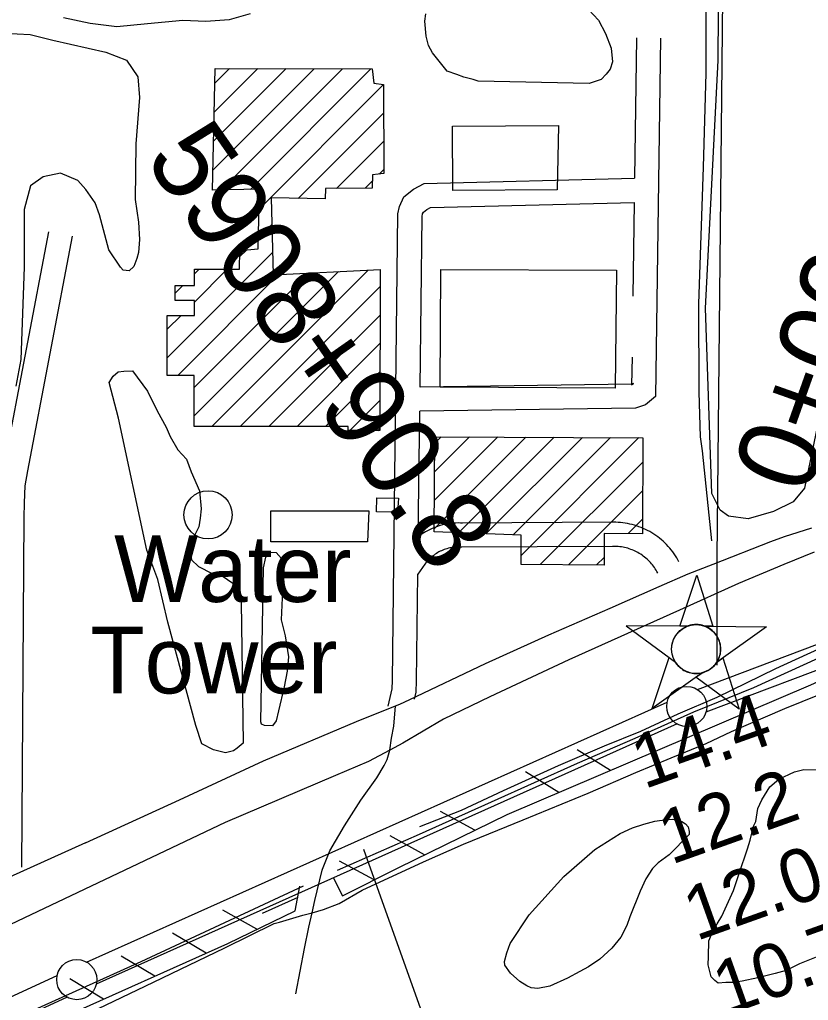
# Model space of a CAD drawing. Extents: x 3598634 to 3636690, y 517270 to 542944.
# Drawn here: x 3613422 to 3614405, y 537102 to 538324 of the extents above; entities that cross this region are included whole.
import ezdxf

# ---------------------------------------------------------------- set-up
doc = ezdxf.new("R2010")
doc.units = 0
for name, color, linetype in [('V-BLDG-OTLN', 7, 'Continuous'), ('V-CHAN-NAID', 7, 'Continuous'), ('V-DOMW-IDEN', 7, 'Continuous'), ('V-DOMW-TANK', 7, 'Continuous'), ('V-FLOD-BASE', 7, 'Continuous'), ('V-LEVE-TOET', 7, 'Continuous'), ('V-RIVR-RANG', 7, 'Continuous'), ('V-ROAD-CNTR', 7, 'Continuous'), ('V-RRAP-FSHR', 7, 'Continuous'), ('V-SITE-VEGE', 7, 'Continuous'), ('V-SURV-IDEN', 7, 'Continuous'), ('V-SURV-LINE', 7, 'Continuous'), ('V-TOPO-BNDY', 7, 'Continuous'), ('V-TOPO-SHOR', 7, 'Continuous')]:
    doc.layers.add(name, color=color, linetype=linetype)

msp = doc.modelspace()

# ---------------------------------------------------------------- linework, layer by layer
at = {"layer": 'V-BLDG-OTLN'}
for p, q in [((3613663.3, 538136.7), (3613789.6, 538263)), ((3613664.1, 538172.8), (3613754.4, 538263.1)), ((3613664.9, 538209), (3613719.2, 538263.3)), ((3613665.7, 538245.1), (3613684, 538263.4)), ((3613673.9, 538111.9), (3613824.8, 538262.9)), ((3613710.1, 538112.7), (3613860.1, 538262.7)), ((3613720.8, 538088.1), (3613875.9, 538243.2)), ((3613769.5, 538101.5), (3613876.1, 538208)), ((3613817.4, 538113.9), (3613876.2, 538172.7)), ((3613870.5, 538131.7), (3613876.2, 538137.5)), ((3613853, 538114.2), (3613862.1, 538123.3)), ((3613720, 538051.9), (3613736.7, 538068.7)), ((3613696.5, 538028.5), (3613705.4, 538037.3)), ((3613606.3, 537902.9), (3613737.5, 538034.1)), ((3613640.2, 538007.5), (3613646.1, 538013.4)), ((3613640.4, 537972.3), (3613681.2, 538013.2)), ((3613619.6, 537880.8), (3613745.2, 538006.5)), ((3613639.7, 537865.6), (3613782.5, 538008.3)), ((3613639.8, 537830.3), (3613819.7, 538010.2)), ((3613662, 537817.2), (3613856.9, 538012.1)), ((3613616.2, 537983.5), (3613625.6, 537992.9)), ((3613697.4, 537817.2), (3613871.8, 537991.6)), ((3613606.3, 537938.3), (3613623.7, 537955.7)), ((3613732.8, 537817.2), (3613871.7, 537956.1)), ((3613768.1, 537817.2), (3613871.5, 537920.6)), ((3613803.5, 537817.3), (3613871.4, 537885.1)), ((3613833.8, 537812.2), (3613871.2, 537849.6)), ((3613869, 537812.1), (3613871.1, 537814.1)), ((3613939.1, 537689.6), (3614053.4, 537803.9)), ((3613939.3, 537725.2), (3614018.2, 537804.1)), ((3613939.6, 537760.8), (3613983, 537804.3)), ((3613939.8, 537796.4), (3613947.8, 537804.4)), ((3613969.4, 537684.6), (3614088.6, 537803.8)), ((3614003.5, 537683.3), (3614123.8, 537803.6)), ((3614037.6, 537682.1), (3614158.9, 537803.4)), ((3614047.4, 537656.5), (3614194.1, 537803.3)), ((3614071.2, 537645), (3614199, 537772.7)), ((3614106.4, 537644.8), (3614198.8, 537737.2)), ((3614180.7, 537683.7), (3614198.6, 537701.7)), ((3614141.5, 537644.6), (3614150.9, 537654))]:
    msp.add_line(p, q, dxfattribs=at)
for points in [[(3613871.9, 538012.8), (3613871.1, 537812.1), (3613831.9, 537812.2), (3613831.9, 537817.3), (3613639.8, 537817.1), (3613639.7, 537880.8), (3613606.3, 537880.8), (3613606.3, 537955.7), (3613640.2, 537955.7), (3613640.4, 537974.2), (3613616.2, 537974.3), (3613616.3, 537993), (3613640.1, 537992.9), (3613640.3, 538013.4), (3613696.5, 538013.1), (3613696.6, 538036.7), (3613719.7, 538038.4), (3613721.3, 538113), (3613662.8, 538111.6), (3613666.1, 538263.5), (3613861.6, 538262.7), (3613863.8, 538245.2), (3613876, 538243.2), (3613876.2, 538132.3), (3613862.2, 538130.9), (3613861.9, 538114.3), (3613803.4, 538113.8), (3613803.1, 538100.7), (3613735.9, 538102.2), (3613738.2, 538006.1)], [(3614092.3, 538112), (3613962.2, 538111.3), (3613961.8, 538191.5), (3614094, 538192.3)], [(3614164.7, 537865.1), (3613946.4, 537866.3), (3613947.2, 538013), (3614166.1, 538011.8)], [(3613939.9, 537804.5), (3614199.1, 537803.2), (3614198.6, 537683.6), (3614151.1, 537683.9), (3614150.9, 537644.5), (3614047.3, 537645.1), (3614047.5, 537681.7), (3613939.1, 537685.8)], [(3613893.3, 537710.3), (3613867.1, 537710.9), (3613867.5, 537728.3), (3613894.6, 537727.8)], [(3613855.9, 537673.6), (3613735.4, 537673.6), (3613735.4, 537711.9), (3613857.5, 537711.9)]]:
    msp.add_lwpolyline(points, close=True, dxfattribs=at)
at = {"layer": 'V-CHAN-NAID'}
for points in [[(3614254.6, 537568.4), (3614245.1, 537568.4), (3614266.2, 537631.9), (3614286.4, 537568.2), (3614276.8, 537568.2), (3614275.2, 537568.8), (3614273.2, 537569.4), (3614271.1, 537569.9), (3614269.1, 537570.2), (3614267.9, 537570.3), (3614266.4, 537570.4), (3614264.7, 537570.4), (3614263.3, 537570.3), (3614261.4, 537570.1), (3614260, 537569.9), (3614258.2, 537569.5), (3614256.7, 537569.1), (3614255.7, 537568.7)], [(3614254.6, 537568.4), (3614178.2, 537568.9), (3614239.7, 537523.5), (3614238.6, 537525.4), (3614237.8, 537527.1), (3614237, 537529), (3614236.3, 537531.1), (3614235.9, 537532.4), (3614235.6, 537534), (3614235.3, 537535.5), (3614235.1, 537537.1), (3614235, 537538.8), (3614235, 537540.4), (3614235.1, 537542.5), (3614235.3, 537544.1), (3614235.7, 537546.3), (3614236.2, 537548.2), (3614236.8, 537550.1), (3614237.4, 537551.8), (3614238.1, 537553.4), (3614239, 537554.9), (3614240, 537556.6), (3614241.1, 537558.1), (3614242.1, 537559.4), (3614243.1, 537560.5), (3614244.4, 537561.9), (3614245.4, 537562.8), (3614247.1, 537564.2), (3614248.3, 537565.1), (3614250, 537566.2), (3614251.8, 537567.1), (3614253.2, 537567.8)], [(3614276.8, 537568.2), (3614353.3, 537567.7), (3614291.1, 537523.2), (3614292, 537524.6), (3614293, 537526.5), (3614293.7, 537528.1), (3614294.5, 537530), (3614295, 537531.8), (3614295.4, 537533.5), (3614295.8, 537535.5), (3614295.9, 537537), (3614296.1, 537539.2), (3614296, 537541.3), (3614295.9, 537543.5), (3614295.6, 537545.3), (3614295.1, 537547.5), (3614294.5, 537549.7), (3614293.7, 537551.6), (3614293.1, 537553.1), (3614292, 537555), (3614291, 537556.7), (3614289.8, 537558.4), (3614288.5, 537560), (3614287.2, 537561.3), (3614285.6, 537562.9), (3614283.9, 537564.3), (3614282.2, 537565.4), (3614280.3, 537566.6), (3614278.8, 537567.3)], [(3614273.1, 537510.2), (3614210.9, 537465.7), (3614232, 537529.2), (3614239.7, 537523.5), (3614240.4, 537522.6), (3614241.7, 537520.7), (3614243, 537519.3), (3614244.4, 537517.8), (3614245.8, 537516.5), (3614247.3, 537515.4), (3614248.7, 537514.4), (3614250.3, 537513.3), (3614252.1, 537512.4), (3614253.8, 537511.6), (3614255.3, 537511.1), (3614256.9, 537510.5), (3614259.1, 537510), (3614260.7, 537509.7), (3614262.7, 537509.4), (3614264.2, 537509.3), (3614266.1, 537509.3), (3614267.8, 537509.4), (3614269.5, 537509.6), (3614271.4, 537509.9)], [(3614291.1, 537523.2), (3614298.9, 537528.7), (3614319.1, 537465), (3614265.3, 537504.7), (3614273.1, 537510.2), (3614274.7, 537510.7), (3614276.4, 537511.3), (3614278.5, 537512.2), (3614280.3, 537513.1), (3614282.1, 537514.2), (3614283.9, 537515.4), (3614285.4, 537516.7), (3614286.7, 537517.8), (3614288.1, 537519.2), (3614289.3, 537520.6), (3614290.4, 537522.1)]]:
    msp.add_lwpolyline(points, close=True, dxfattribs=at)
msp.add_circle((3614265.5, 537539.8), 30.5, dxfattribs=at)
at = {"layer": 'V-DOMW-TANK'}
msp.add_line((3613657.2, 537707.1), (3613657.2, 537707.1), dxfattribs=at)
msp.add_circle((3613657.2, 537707.1), 30, dxfattribs=at)
at = {"layer": 'V-FLOD-BASE'}
for points in [[(3613818.4, 537264.3), (3613920.8, 537309.1), (3614010.3, 537349.6), (3614117.8, 537397.6), (3614189.6, 537428.9), (3614262.7, 537461.5), (3614337.4, 537491.9), (3614418.4, 537528.8), (3614443.6, 537539.9), (3614467.1, 537547.7), (3614485.5, 537554), (3614501.9, 537558.6), (3614582, 537571.4), (3614669.6, 537584.5), (3614759.3, 537597.6), (3614850.6, 537607.7), (3614935.7, 537619.5), (3615037.5, 537631.5), (3615059.1, 537633.5)], [(3613775.6, 537244.3), (3613573.5, 537149.9), (3613380.6, 537063.3), (3613203.1, 536981.9), (3613149.4, 536956.7)]]:
    msp.add_lwpolyline(points, dxfattribs=at)
at = {"layer": 'V-LEVE-TOET'}
for points in [[(3614412.5, 537660.4), (3614374.8, 537645.4), (3614318.5, 537621.6), (3614244.6, 537588.3), (3614106.9, 537526.4), (3614008.5, 537480.2), (3613950.5, 537452.4), (3613900, 537422.7), (3613883.8, 537414), (3613857, 537399.5), (3613815.9, 537382.1), (3613678.7, 537323.7)], [(3613975.6, 537296.6), (3614050.1, 537327.1), (3614131.1, 537360.3), (3614190.3, 537386.1), (3614234.4, 537404.3), (3614278, 537422), (3614309.6, 537437.2), (3614375.9, 537465.7), (3614440.9, 537492.1)], [(3613678.7, 537323.7), (3613393.9, 537188.7), (3613238.5, 537113.5), (3613220.5, 537105.5), (3613196.7, 537095), (3613084.3, 537034.7), (3612874.5, 536938.8), (3612572.5, 536804.8), (3612341.7, 536695.8), (3612081.2, 536565.6), (3611875, 536468.3), (3611591.1, 536315.1), (3611373.7, 536204.3), (3611078.2, 536045.7), (3610830.8, 535920.2)], [(3613480.6, 537072.8), (3613589, 537124.6), (3613678, 537167.4), (3613739.7, 537197.9), (3613746.3, 537199.5), (3613775.2, 537208.1), (3613786.8, 537211.3), (3613800.9, 537215.2), (3613820.6, 537222.7), (3613849.4, 537239.5), (3613925.9, 537274.5), (3613975.6, 537296.6)]]:
    msp.add_lwpolyline(points, dxfattribs=at)
at = {"layer": 'V-RIVR-RANG'}
msp.add_line((3613850.9, 537290.3), (3614214.6, 536273.3), dxfattribs=at)
at = {"layer": 'V-ROAD-CNTR'}
for points in [[(3614221.2, 538301), (3614214.9, 537854.7), (3614202.3, 537844.1), (3614189.8, 537840.1), (3613921, 537836.2)], [(3614191.2, 538301.5), (3614188.7, 538126.5)], [(3613881.5, 537468.7), (3613886.8, 537490.2), (3613887.1, 537500.8), (3613893.9, 538082.3), (3613895.9, 538091.5), (3613901.3, 538103.5), (3613913.1, 538112.8), (3613926.4, 538119.9), (3614188.7, 538126.5)], [(3613921.4, 537866.2), (3613923.9, 538078.9), (3613924.5, 538082.1), (3613925.6, 538084.4), (3613929.7, 538087.6), (3613934.3, 538090.1), (3614188.3, 538096.5)], [(3614188.3, 538096.5), (3614186.7, 537979.5)], [(3613395.2, 537256.1), (3613397.8, 537704.4), (3613398.5, 537723), (3613399.2, 537746.3), (3613402.9, 537767.4), (3613458.9, 538059.9)], [(3613425.3, 537268), (3613427.8, 537703.7), (3613428.5, 537722), (3613429.1, 537743.2), (3613432.4, 537762), (3613488.3, 538054.2)], [(3614185.6, 537903.4), (3614185.1, 537868.9), (3614187.4, 537870.8), (3614184.8, 537870), (3613921.4, 537866.2)], [(3613919.2, 537680.1), (3613921, 537836.2)], [(3613974.3, 537696.8), (3613971.7, 537696.9), (3613968.9, 537697), (3613966.1, 537696.9), (3613963.2, 537696.7), (3613960.4, 537696.5), (3613957.6, 537696.1), (3613954.8, 537695.7), (3613952, 537695.1), (3613949.3, 537694.5), (3613946.6, 537693.7), (3613943.8, 537692.9), (3613941.2, 537691.9), (3613938.5, 537690.9), (3613935.9, 537689.8), (3613933.4, 537688.6), (3613930.8, 537687.3), (3613928.4, 537685.9), (3613926, 537684.5), (3613919.2, 537680.1)], [(3614161, 537697.8), (3613973.5, 537696.8)], [(3614244.1, 537648.7), (3614242.8, 537651), (3614241.4, 537653.6), (3614239.8, 537656.1), (3614238.1, 537658.6), (3614236.4, 537661), (3614234.6, 537663.3), (3614232.7, 537665.6), (3614230.7, 537667.8), (3614228.7, 537670), (3614226.6, 537672.1), (3614224.5, 537674.1), (3614222.2, 537676.1), (3614220, 537677.9), (3614217.6, 537679.7), (3614215.2, 537681.5), (3614212.7, 537683.1), (3614210.2, 537684.7), (3614207.7, 537686.2), (3614205.1, 537687.6), (3614202.4, 537688.9), (3614199.7, 537690.1), (3614197, 537691.3), (3614194.2, 537692.3), (3614191.4, 537693.3), (3614188.6, 537694.2), (3614185.7, 537695), (3614182.9, 537695.6), (3614180, 537696.2), (3614177, 537696.7), (3614174.1, 537697.2), (3614171.2, 537697.5), (3614168.2, 537697.7), (3614165.3, 537697.8), (3614162.3, 537697.8), (3614160.9, 537697.8)], [(3614358.8, 537673.9), (3614375.7, 537679.9), (3614392.7, 537685.6), (3614409.8, 537691.1)], [(3613504.4, 537298.2), (3613621.5, 537352.1), (3613726.5, 537400.6), (3613842.4, 537449.7), (3613890.9, 537468.9), (3613896.1, 537471), (3613908.6, 537477), (3614002.8, 537521.9), (3614081.8, 537557.6), (3614158.2, 537590.9), (3614219.5, 537617.9), (3614255.6, 537633.7), (3614286.6, 537645.5), (3614358.8, 537673.9)], [(3613972.9, 537666.9), (3613970.9, 537667), (3613969.1, 537667), (3613967.3, 537666.9), (3613965.5, 537666.8), (3613963.7, 537666.7), (3613962, 537666.4), (3613960.2, 537666.1), (3613958.4, 537665.8), (3613956.7, 537665.4), (3613954.9, 537664.9), (3613953.2, 537664.4), (3613951.5, 537663.8), (3613949.9, 537663.1), (3613948.2, 537662.4), (3613946.6, 537661.7), (3613945, 537660.8), (3613943.4, 537660), (3613941.9, 537659), (3613940.4, 537658.1), (3613938.9, 537657), (3613937.5, 537656), (3613936.1, 537654.8), (3613934.7, 537653.6), (3613933.4, 537652.4), (3613932.2, 537651.2), (3613930.9, 537649.8), (3613929.8, 537648.5), (3613928.6, 537647.1), (3613927.5, 537645.7), (3613918.6, 537633)], [(3614161.2, 537667.8), (3613973.7, 537666.8)], [(3614217.7, 537634.4), (3614216.7, 537636.4), (3614215.7, 537638.1), (3614214.6, 537639.8), (3614213.5, 537641.4), (3614212.3, 537643), (3614211.1, 537644.6), (3614209.9, 537646.1), (3614208.5, 537647.6), (3614207.2, 537649.1), (3614205.8, 537650.5), (3614204.3, 537651.9), (3614202.8, 537653.2), (3614201.3, 537654.4), (3614199.7, 537655.7), (3614198.1, 537656.8), (3614196.4, 537657.9), (3614194.7, 537659), (3614193, 537660), (3614191.3, 537660.9), (3614189.5, 537661.8), (3614187.7, 537662.6), (3614185.8, 537663.4), (3614184, 537664.1), (3614182.1, 537664.8), (3614180.2, 537665.4), (3614178.3, 537665.9), (3614176.3, 537666.4), (3614174.4, 537666.8), (3614172.4, 537667.1), (3614170.4, 537667.4), (3614168.5, 537667.6), (3614166.5, 537667.7), (3614164.5, 537667.8), (3614162.4, 537667.8), (3614161.3, 537667.8)], [(3613914.5, 537477.3), (3613916.7, 537486.2), (3613917.1, 537500.3), (3613918.6, 537633)], [(3613921.3, 537318.5), (3613973, 537339.2), (3614025.6, 537363.4), (3614094, 537394.8), (3614151.5, 537419.3), (3614196.4, 537437.5), (3614243.1, 537459), (3614291.8, 537480), (3614364.9, 537515.8), (3614418.3, 537540)], [(3613799.9, 537265.7), (3613808.9, 537288.2), (3613827.1, 537319.4), (3613847.7, 537351.4), (3613867.5, 537379.2), (3613876.9, 537394.8), (3613880.4, 537402.2), (3613883.8, 537414), (3613886, 537428.7), (3613888.8, 537443.7), (3613890.9, 537468.9)], [(3613504.4, 537298.2), (3613263.1, 537189.7), (3613226.2, 537173.1), (3612904, 537025.3), (3612651.7, 536909.6), (3612381.2, 536778.2), (3612102.9, 536636.7), (3612024.4, 536597.3), (3611881, 536525.3), (3611648.7, 536408.9), (3611528.5, 536348.3), (3611374.7, 536270.8), (3611116.8, 536138.9), (3611045.6, 536103.1), (3610844.5, 536002)], [(3613766.8, 537110.3), (3613777.2, 537166.6), (3613782.7, 537193.1), (3613786.8, 537211.3), (3613790.1, 537226.3), (3613799.3, 537264.2), (3613799.9, 537265.7)]]:
    msp.add_lwpolyline(points, dxfattribs=at)
at = {"layer": 'V-RRAP-FSHR'}
for p, q in [((3614158.9, 537388.6), (3614117.4, 537414.4)), ((3614094.5, 537361.1), (3614053, 537386.9)), ((3613989.8, 537314), (3613947.1, 537337.6)), ((3613926.9, 537283.3), (3613884.2, 537307)), ((3613864.2, 537252.2), (3613821.2, 537275.3)), ((3613769, 537230.3), (3613724.5, 537210.1)), ((3613718.1, 537190.6), (3613675.5, 537214.4)), ((3613654.7, 537160.9), (3613612.8, 537185.9)), ((3613590.8, 537132.2), (3613548.9, 537157.3)), ((3613527, 537103.6), (3613485, 537128.7))]:
    msp.add_line(p, q, dxfattribs=at)
for points in [[(3614030.1, 537333.6), (3614408.3, 537495.2), (3614429.4, 537504.9), (3614466.2, 537516.7), (3614501.1, 537529), (3614548.3, 537541.9), (3614614, 537550.4), (3615084.7, 537615.1)], [(3614030.1, 537333.6), (3614177.8, 537396.7)], [(3613813, 537255.2), (3613824.6, 537232.3), (3613895, 537267.7), (3614030.1, 537333.6)], [(3613155.1, 536958.6), (3613162.6, 536940), (3613281.4, 536983.3), (3613470.5, 537078.3), (3613681.8, 537173), (3613765.9, 537213.7), (3613771.6, 537244.3)], [(3613256, 536974.1), (3613281.4, 536983.3), (3613470.5, 537078.3), (3613681.8, 537173), (3613765.9, 537213.7), (3613771.6, 537244.3)]]:
    msp.add_lwpolyline(points, dxfattribs=at)
at = {"layer": 'V-SITE-VEGE'}
for points in [[(3614295.5, 538637.1), (3614413.4, 538673.3), (3614421.4, 538666), (3614431.9, 538654), (3614446.5, 538617.7), (3614461.1, 538459.7), (3614445.4, 538024), (3614416.6, 537818.3), (3614400.5, 537740.3), (3614386.6, 537723.5), (3614362, 537711.4), (3614330.3, 537702.2), (3614306, 537705.4), (3614295.4, 537712.8), (3614285, 537733.8), (3614277.4, 537964.6), (3614293.1, 538273.2)], [(3613563.2, 537886.7), (3613581.6, 537861.1), (3613593.7, 537836.5), (3613604.9, 537816.5), (3613610.1, 537804.6), (3613619.6, 537788.2), (3613630.2, 537776.3), (3613636.2, 537760.8), (3613646.5, 537737.2), (3613648.7, 537714.6), (3613647.5, 537702.9), (3613645.5, 537692.2), (3613639.8, 537680.6), (3613636, 537668.9), (3613635.7, 537656.3), (3613636.5, 537650.9), (3613645.3, 537642.6), (3613662.3, 537634.1), (3613674.8, 537631.2), (3613688.1, 537621.9), (3613698.4, 537598.2), (3613700.9, 537422.5), (3613693.6, 537416.3), (3613689, 537412.8), (3613679.1, 537410.3), (3613663.8, 537414.3), (3613649.6, 537421.8), (3613642, 537444.5), (3613606.9, 537573.2), (3613594.5, 537626.6), (3613580.9, 537662.9), (3613545.7, 537827.6), (3613534.1, 537872), (3613538.8, 537880), (3613545.2, 537885.3), (3613552.4, 537886.1)], [(3613723.1, 537449), (3613726.4, 537640.9), (3613729.4, 537654.3), (3613733.1, 537660.5), (3613742.1, 537660.3), (3613751.8, 537649.3), (3613748.4, 537576.4), (3613753.4, 537556.5), (3613757.3, 537530.3), (3613756, 537512.3), (3613752, 537492.6), (3613745.1, 537463), (3613742.1, 537450.4), (3613737.4, 537444.2), (3613727.5, 537444.4), (3613724, 537446.3)], [(3614256.9, 537308.8), (3614231.8, 537283.3), (3614218.3, 537273.4), (3614211, 537266.3), (3614203, 537253.5), (3614195.8, 537238.3), (3614182.7, 537206.1), (3614179, 537195.5), (3614171.6, 537180.9), (3614160.3, 537167), (3614145.3, 537153.4), (3614131.5, 537144), (3614120.5, 537138.1), (3614105, 537129.5), (3614083.1, 537119.6), (3614068.3, 537116.8), (3614060, 537117.7), (3614054.5, 537120), (3614045.6, 537125.7), (3614034, 537135.9), (3614026.9, 537146), (3614026.7, 537150.5), (3614029.4, 537161.1), (3614033.6, 537172.9), (3614057.5, 537208.5), (3614100.5, 537256.2), (3614139.4, 537289.9), (3614170.7, 537310.1), (3614186.2, 537317), (3614200.3, 537321.6), (3614214.1, 537325.2), (3614229.2, 537327.5), (3614236.2, 537327.8), (3614242.2, 537326.6), (3614247.5, 537324.8), (3614252.3, 537322.1), (3614255.6, 537318.4), (3614256.9, 537312.6)]]:
    msp.add_lwpolyline(points, close=True, dxfattribs=at)
for points in [[(3613709.8, 538331.3), (3613683.5, 538323.8), (3613654.6, 538321.7), (3613625.8, 538323.2), (3613581.6, 538318.8), (3613543.6, 538315.1), (3613510.4, 538319.4), (3613477.2, 538326.4)], [(3614131.5, 538336.9), (3614143.8, 538323.6), (3614152.5, 538307.1), (3614159.8, 538288.5), (3614161.2, 538271.8), (3614158.3, 538262.4), (3614153.6, 538256.2), (3614147.2, 538249.5), (3614132.2, 538244.4), (3613993.8, 538247.4), (3613987.5, 538249.4), (3613975.8, 538252.3), (3613967.3, 538255.7), (3613955.3, 538260), (3613936.8, 538282.9), (3613932.1, 538292.1), (3613929.1, 538303.8), (3613927.3, 538322.4), (3613928.8, 538331.4)], [(3613403.2, 538307.4), (3613435.4, 538305.8), (3613463.8, 538298.7), (3613529.8, 538283.5), (3613555.4, 538273.7), (3613569.7, 538253.1), (3613571.9, 538227.3), (3613567, 538169.3), (3613566.4, 538100.2), (3613570.4, 538071.6), (3613571.8, 538050.4), (3613570.5, 538033.8), (3613568.5, 538026.5), (3613564.6, 538016.4), (3613558.9, 538011), (3613551.6, 538012.1), (3613548, 538015.9), (3613533.7, 538037.4), (3613521.7, 538080.9), (3613516.5, 538095.8), (3613504.9, 538112.6), (3613495, 538123.9), (3613473.1, 538132.7), (3613451.8, 538128.5), (3613435.9, 538116.9), (3613427.9, 538087.6), (3613428.2, 538015.7), (3613423.9, 537900.6), (3613417.6, 537867.5)], [(3614417.1, 537156.9), (3614394.5, 537147.6), (3614377.8, 537139.2), (3614364.1, 537135.7), (3614342.6, 537130.3), (3614323.1, 537125.8), (3614312.3, 537124.1), (3614302.6, 537124.3), (3614292.9, 537123.6), (3614289, 537126.6), (3614284.3, 537131.5), (3614280.7, 537146.2), (3614280.9, 537156.9), (3614281.4, 537176.3), (3614284.5, 537184.1), (3614291.6, 537197.5), (3614297.6, 537207.1), (3614311.9, 537238.9), (3614319.2, 537260.1), (3614329.5, 537291), (3614332.7, 537301.6), (3614337, 537319.1), (3614340, 537324.8), (3614342.3, 537341.3), (3614347.4, 537351.9), (3614357.5, 537368.2), (3614368.4, 537377.7), (3614388, 537387), (3614399.7, 537389.7), (3614430.9, 537389)]]:
    msp.add_lwpolyline(points, dxfattribs=at)
at = {"layer": 'V-SURV-LINE'}
for points in [[(3614267.2, 537489.4), (3614454.3, 537560)], [(3614464.9, 537531.9), (3614277.8, 537461.3)], [(3613505.7, 537149.7), (3614229.4, 537473.8)], [(3614241.7, 537446.5), (3613517.9, 537122.3)], [(3612561.5, 536714.6), (3613469.2, 537133.1)], [(3613481.7, 537105.9), (3612574.1, 536687.3)]]:
    msp.add_lwpolyline(points, dxfattribs=at)
for centre in [(3614253.8, 537468.3), (3613493.6, 537127.9)]:
    msp.add_circle(centre, 25, dxfattribs=at)
at = {"layer": 'V-TOPO-BNDY'}
for p, q in [((3614291.7, 537653.5), (3614325.3, 540967.5)), ((3614291.8, 537519.9), (3614291.7, 537653.5))]:
    msp.add_line(p, q, dxfattribs=at)
at = {"layer": 'V-TOPO-SHOR'}
msp.add_lwpolyline([(3614285.2, 537674.7), (3614273.6, 537786.8), (3614271.1, 537804.4), (3614269.3, 537860.1), (3614268.8, 537970.2), (3614274.8, 538140.5), (3614277.9, 538257.6), (3614277.8, 538413.4), (3614283.2, 538584.9), (3614282.5, 538643.4)], dxfattribs=at)

# ---------------------------------------------------------------- texts
at = {"layer": 'V-DOMW-IDEN'}
for s, p in [('Water', (3613540.1, 537598.5)), (' Tower', (3613479.5, 537484.6))]:
    msp.add_text(s, height=83, dxfattribs=at).set_placement(p)
at = {"layer": 'V-RIVR-RANG'}
for s, p in [('14.4', (3614200.6, 537364.9)), ('12.2', (3614234.4, 537270.8)), ('12.0', (3614265.6, 537175.7)), ('10.7', (3614302.2, 537082.6))]:
    msp.add_text(s, height=67, rotation=19.6483, dxfattribs=at).set_placement(p)
at = {"layer": 'V-SURV-IDEN'}
for s, rotation, p in [('5908+90.8', 304.957, (3613576.8, 538150.5)), ('0+00.0', 70.4488, (3614403.7, 537729.2))]:
    msp.add_text(s, height=100, rotation=rotation, dxfattribs=at).set_placement(p)

doc.saveas('drawing.dxf')
